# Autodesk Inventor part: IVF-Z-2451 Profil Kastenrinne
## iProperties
Created: 2009-09
Part Number: IVF-Z-2451 Profil Kastenrinne
Material: Stahl (hohe Festigk., niedr. Legier.)
Document SubType Name: Sheet Metal
Designer: Strathkötter
Density: 7.84 g/cm^3
Mass: 6888.12 g
Surface Area: 8854.89 cm^2
Volume: 878.587 cm^3
Author: Strathkötter
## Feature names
1. Extrusion2
2. Extrusion3
3. Grobblech1
4. Grobblech3
5. Biegung2
6. Grobblech4
7. Biegung3
8. Grobblech5
9. Biegung4
10. Grobblech6
11. Biegung5
12. Grobblech7
13. Biegung6
14. Grobblech8
15. Biegung7
16. Grobblech9
17. Biegung8
18. Grobblech10
19. Biegung9
20. Grobblech11
21. Biegung10
22. Grobblech12
23. Biegung11
